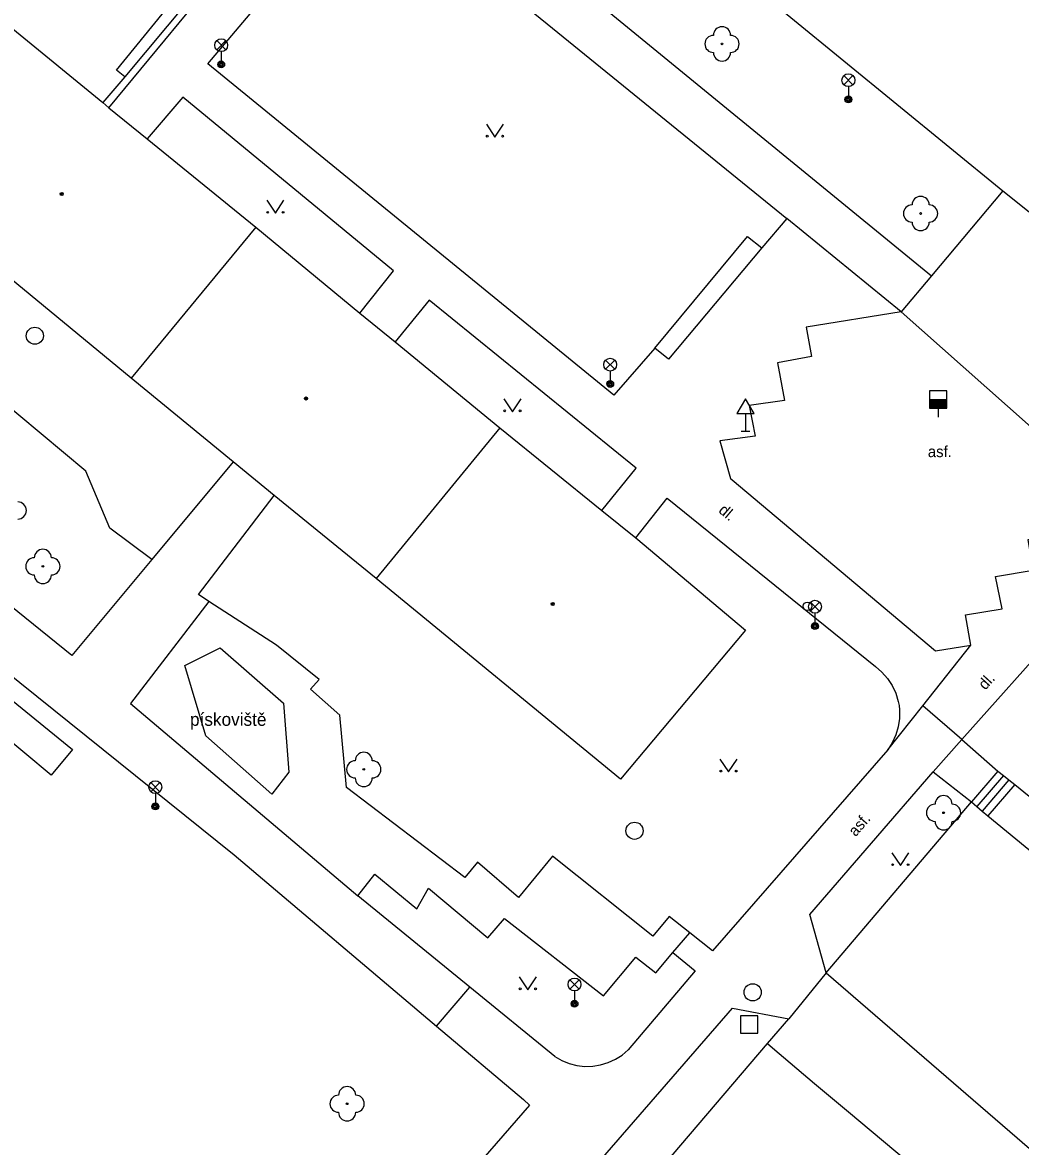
# Model space of a CAD drawing. Extents: x -598932 to -598196, y -1162207 to -1161504.
# Drawn here: x -598545.9 to -598487.7, y -1161944.1 to -1161878.5 of the extents above; entities that cross this region are included whole.
import ezdxf

# ---------------------------------------------------------------- set-up
doc = ezdxf.new("R2010")
doc.units = 0
for name, color, linetype in [('Level 22', 7, 'Continuous'), ('Level 26', 7, 'Continuous'), ('Level 27', 7, 'Continuous'), ('Level 28', 7, 'Continuous'), ('Level 33', 7, 'Continuous'), ('Level 34', 7, 'Continuous'), ('Level 36', 7, 'Continuous'), ('Level 39', 7, 'Continuous'), ('specificka linie pasportu komunikaci', 7, 'Continuous'), ('TM - budovy zdene_ betonove - VP', 7, 'Continuous'), ('TM - chodniky - VP', 7, 'Continuous'), ('TM - komunikace - VP', 7, 'Continuous'), ('TM - letecke snimky - pomocna linie', 7, 'Continuous'), ('TM - plot dreveny_ kovovy - VP', 7, 'Continuous'), ('TM - popis povrchu', 7, 'Continuous'), ('TM - poznamka', 7, 'Continuous'), ('TM - rozhrani ploch obecne - VP', 7, 'Continuous'), ('TM - schody - VP', 7, 'Continuous'), ('TM - vjezd na pozemek', 7, 'Continuous')]:
    doc.layers.add(name, color=color, linetype=linetype)

msp = doc.modelspace()

# ---------------------------------------------------------------- linework, layer by layer
at = {"layer": 'Level 22'}
for centre in [(-598505.14, -1161879.76), (-598493.56, -1161889.65), (-598544.74, -1161910.23), (-598526.03, -1161922.07), (-598492.22, -1161924.6), (-598527, -1161941.57)]:
    msp.add_circle(centre, 0.05, dxfattribs=at)
for centre, start, end in [((-598505.14, -1161879.26), 0, 180), ((-598505.64, -1161879.76), 90, 270), ((-598504.64, -1161879.76), 270, 90), ((-598505.14, -1161880.26), 180, 0), ((-598493.56, -1161889.15), 0, 180), ((-598494.06, -1161889.65), 90, 270), ((-598493.06, -1161889.65), 270, 90), ((-598493.56, -1161890.15), 180, 0), ((-598546.2, -1161906.97), 270, 90), ((-598544.74, -1161909.73), 0, 180), ((-598545.24, -1161910.23), 90, 270), ((-598544.24, -1161910.23), 270, 90), ((-598544.74, -1161910.73), 180, 0), ((-598526.03, -1161921.57), 0, 180), ((-598526.53, -1161922.07), 90, 270), ((-598525.53, -1161922.07), 270, 90), ((-598526.03, -1161922.57), 180, 0), ((-598492.22, -1161924.1), 0, 180), ((-598492.72, -1161924.6), 90, 270), ((-598491.72, -1161924.6), 270, 90), ((-598492.22, -1161925.1), 180, 0), ((-598527, -1161941.07), 0, 180), ((-598527.5, -1161941.57), 90, 270), ((-598526.5, -1161941.57), 270, 90), ((-598527, -1161942.07), 180, 0)]:
    msp.add_arc(centre, 0.5, start, end, dxfattribs=at)
at = {"layer": 'Level 26'}
msp.add_lwpolyline([(-598504.06, -1161937.45), (-598503.06, -1161937.45), (-598503.06, -1161936.45), (-598504.06, -1161936.45)], close=True, dxfattribs=at)
at = {"layer": 'Level 27'}
for centre in [(-598545.21, -1161896.78), (-598510.24, -1161925.65), (-598503.35, -1161935.07)]:
    msp.add_circle(centre, 0.5, dxfattribs=at)
at = {"layer": 'Level 28'}
for p, q in [((-598493.04, -1161900.5), (-598492.04, -1161900.5)), ((-598493.04, -1161900.55), (-598492.04, -1161900.55)), ((-598493.04, -1161900.6), (-598492.04, -1161900.6)), ((-598493.04, -1161900.65), (-598492.04, -1161900.65)), ((-598493.04, -1161900.7), (-598492.04, -1161900.7)), ((-598493.04, -1161900.75), (-598492.04, -1161900.75)), ((-598493.04, -1161900.8), (-598492.04, -1161900.8)), ((-598493.04, -1161900.85), (-598492.04, -1161900.85)), ((-598493.04, -1161900.9), (-598492.04, -1161900.9)), ((-598493.04, -1161900.95), (-598492.04, -1161900.95)), ((-598492.54, -1161901), (-598492.54, -1161901.53))]:
    msp.add_line(p, q, dxfattribs=at)
msp.add_lwpolyline([(-598493.04, -1161901), (-598492.04, -1161901), (-598492.04, -1161900), (-598493.04, -1161900)], close=True, dxfattribs=at)
msp.add_circle((-598500.16, -1161912.56), 0.25, dxfattribs=at)
at = {"layer": 'Level 33'}
for p, q in [((-598534.605, -1161880.1), (-598534.075, -1161879.57)), ((-598534.605, -1161879.57), (-598534.075, -1161880.1)), ((-598534.34, -1161880.21), (-598534.34, -1161880.96)), ((-598498.035, -1161882.14), (-598497.505, -1161881.61)), ((-598498.035, -1161881.61), (-598497.505, -1161882.14)), ((-598497.77, -1161882.25), (-598497.77, -1161883)), ((-598511.925, -1161898.73), (-598511.395, -1161898.2)), ((-598511.925, -1161898.2), (-598511.395, -1161898.73)), ((-598511.66, -1161898.84), (-598511.66, -1161899.59)), ((-598499.985, -1161912.85), (-598499.455, -1161912.32)), ((-598499.985, -1161912.32), (-598499.455, -1161912.85)), ((-598499.72, -1161912.96), (-598499.72, -1161913.71)), ((-598538.445, -1161923.37), (-598537.915, -1161922.84)), ((-598538.445, -1161922.84), (-598537.915, -1161923.37)), ((-598538.18, -1161923.48), (-598538.18, -1161924.23)), ((-598514.005, -1161934.88), (-598513.475, -1161934.35)), ((-598514.005, -1161934.35), (-598513.475, -1161934.88)), ((-598513.74, -1161934.99), (-598513.74, -1161935.74))]:
    msp.add_line(p, q, dxfattribs=at)
for centre, radius in [((-598534.34, -1161879.835), 0.375), ((-598534.34, -1161880.96), 0.2), ((-598534.34, -1161880.96), 0.145), ((-598534.34, -1161880.96), 0.0876), ((-598497.77, -1161881.875), 0.375), ((-598497.77, -1161883), 0.2), ((-598497.77, -1161883), 0.145), ((-598497.77, -1161883), 0.0876), ((-598511.66, -1161898.465), 0.375), ((-598511.66, -1161899.59), 0.2), ((-598511.66, -1161899.59), 0.145), ((-598511.66, -1161899.59), 0.0876), ((-598499.72, -1161912.585), 0.375), ((-598499.72, -1161913.71), 0.2), ((-598499.72, -1161913.71), 0.145), ((-598499.72, -1161913.71), 0.0876), ((-598538.18, -1161923.105), 0.375), ((-598538.18, -1161924.23), 0.2), ((-598538.18, -1161924.23), 0.145), ((-598538.18, -1161924.23), 0.0876), ((-598513.74, -1161934.615), 0.375), ((-598513.74, -1161935.74), 0.2), ((-598513.74, -1161935.74), 0.145), ((-598513.74, -1161935.74), 0.0876)]:
    msp.add_circle(centre, radius, dxfattribs=at)
at = {"layer": 'Level 34'}
for p, q in [((-598503.77, -1161901.322), (-598503.77, -1161902.34)), ((-598504.02, -1161902.34), (-598503.52, -1161902.34))]:
    msp.add_line(p, q, dxfattribs=at)
msp.add_lwpolyline([(-598504.27, -1161901.322), (-598503.27, -1161901.322), (-598503.77, -1161900.456)], close=True, dxfattribs=at)
at = {"layer": 'Level 36'}
for points in [[(-598518.88, -1161884.44), (-598518.38, -1161885.19), (-598517.88, -1161884.44)], [(-598531.68, -1161888.88), (-598531.18, -1161889.63), (-598530.68, -1161888.88)], [(-598517.86, -1161900.46), (-598517.36, -1161901.21), (-598516.86, -1161900.46)], [(-598505.26, -1161921.47), (-598504.76, -1161922.22), (-598504.26, -1161921.47)], [(-598495.24, -1161926.93), (-598494.74, -1161927.68), (-598494.24, -1161926.93)], [(-598516.96, -1161934.17), (-598516.46, -1161934.92), (-598515.96, -1161934.17)]]:
    msp.add_lwpolyline(points, dxfattribs=at)
for centre in [(-598518.83, -1161885.14), (-598517.931, -1161885.14), (-598531.63, -1161889.58), (-598530.731, -1161889.58), (-598517.81, -1161901.16), (-598516.911, -1161901.16), (-598505.21, -1161922.17), (-598504.311, -1161922.17), (-598495.19, -1161927.63), (-598494.291, -1161927.63), (-598516.91, -1161934.87), (-598516.011, -1161934.87)]:
    msp.add_circle(centre, 0.05, dxfattribs=at)
at = {"layer": 'Level 39'}
for centre, radius in [((-598543.64, -1161888.51), 0.09), ((-598543.64, -1161888.51), 0.0398), ((-598529.4, -1161900.44), 0.09), ((-598529.4, -1161900.44), 0.0398), ((-598515.01, -1161912.42), 0.09), ((-598515.01, -1161912.42), 0.0398)]:
    msp.add_circle(centre, radius, dxfattribs=at)
at = {"layer": 'specificka linie pasportu komunikaci'}
for points in [[(-598486.09, -1161903.02), (-598494.7, -1161895.38)], [(-598508.01, -1161932.75), (-598507.01, -1161931.61)], [(-598521.79, -1161937.04), (-598519.84, -1161934.78)]]:
    msp.add_lwpolyline(points, dxfattribs=at)
at = {"layer": 'TM - budovy zdene_ betonove - VP'}
for points in [[(-598546.49, -1161878.88), (-598541.24, -1161883.18)], [(-598541.24, -1161883.18), (-598540.89, -1161883.48)], [(-598540.89, -1161883.48), (-598538.66, -1161885.3)], [(-598538.66, -1161885.3), (-598532.32, -1161890.45)], [(-598539.6, -1161899.25), (-598553.72, -1161887.6)], [(-598532.32, -1161890.45), (-598539.6, -1161899.25)], [(-598532.32, -1161890.45), (-598526.25, -1161895.47)], [(-598526.25, -1161895.47), (-598524.19, -1161897.14)], [(-598524.19, -1161897.14), (-598518.09, -1161902.15)], [(-598533.65, -1161904.14), (-598539.6, -1161899.25)], [(-598518.09, -1161902.15), (-598525.3, -1161910.94)], [(-598518.09, -1161902.15), (-598512.15, -1161906.98)], [(-598531.25, -1161906.1), (-598533.65, -1161904.14)], [(-598525.3, -1161910.94), (-598531.25, -1161906.1)], [(-598512.15, -1161906.98), (-598510.17, -1161908.57)], [(-598510.17, -1161908.57), (-598503.77, -1161913.96)], [(-598511.05, -1161922.65), (-598525.3, -1161910.94)], [(-598503.77, -1161913.96), (-598511.05, -1161922.65)], [(-598526.29, -1161965.99), (-598502.49, -1161938.05)], [(-598502.49, -1161938.05), (-598502.19, -1161938.3)], [(-598502.19, -1161938.3), (-598499.74, -1161940.39)], [(-598499.74, -1161940.39), (-598497.76, -1161942.05)], [(-598497.76, -1161942.05), (-598494.41, -1161944.87)]]:
    msp.add_lwpolyline(points, dxfattribs=at)
at = {"layer": 'TM - chodniky - VP'}
for points in [[(-598530.4, -1161862.6), (-598492.92, -1161893.29)], [(-598603.15, -1161870.38), (-598584.47, -1161885.72), (-598557.6, -1161907.74), (-598533.59, -1161927.06)], [(-598511.45, -1161900.24), (-598535.13, -1161880.92), (-598525.89, -1161870), (-598501.37, -1161889.95)], [(-598540.89, -1161883.48), (-598533.52, -1161874.57)], [(-598526.25, -1161895.47), (-598524.3, -1161892.99), (-598536.57, -1161882.87), (-598538.66, -1161885.3)], [(-598538.39, -1161909.83), (-598540.84, -1161908), (-598542.23, -1161904.67), (-598550.07, -1161898.15), (-598555.22, -1161899.67), (-598559.74, -1161895.99), (-598557.48, -1161892.2), (-598559.61, -1161890.72), (-598558.55, -1161889.53), (-598560.88, -1161887.56), (-598561.78, -1161888.66), (-598563.39, -1161887.27)], [(-598501.37, -1161889.95), (-598502.81, -1161891.66)], [(-598502.81, -1161891.66), (-598508.26, -1161898.15), (-598509.06, -1161897.51)], [(-598512.15, -1161906.98), (-598510.14, -1161904.5), (-598522.22, -1161894.71), (-598524.19, -1161897.14)], [(-598509.06, -1161897.51), (-598511.45, -1161900.24)], [(-598533.65, -1161904.14), (-598538.39, -1161909.83)], [(-598535.07, -1161912.27), (-598535.67, -1161911.88), (-598531.25, -1161906.1)], [(-598510.17, -1161908.57), (-598508.33, -1161906.25), (-598496.19, -1161916.07)], [(-598479.84, -1161907.65), (-598491.16, -1161920.33)], [(-598515.02, -1161927.14), (-598517.01, -1161929.55), (-598519.4, -1161927.49), (-598520.13, -1161928.38), (-598527.04, -1161923.13), (-598527.42, -1161918.9), (-598529.14, -1161917.4), (-598528.63, -1161916.83), (-598531.12, -1161914.82), (-598535.07, -1161912.27)], [(-598496.19, -1161916.07), (-598495.812, -1161916.392), (-598495.485, -1161916.765), (-598495.214, -1161917.181), (-598495.006, -1161917.632), (-598494.865, -1161918.107), (-598494.82, -1161918.35), (-598494.793, -1161918.598), (-598494.792, -1161919.095), (-598494.863, -1161919.586), (-598495.003, -1161920.062), (-598495.21, -1161920.513), (-598495.48, -1161920.93)], [(-598491.16, -1161920.33), (-598489.05, -1161922.17)], [(-598495.48, -1161920.93), (-598505.7, -1161932.65)], [(-598499.07, -1161933.94), (-598500.02, -1161930.53), (-598492.83, -1161922.22)], [(-598492.83, -1161922.22), (-598490.59, -1161923.96)], [(-598489.05, -1161922.17), (-598488.73, -1161922.43)], [(-598488.73, -1161922.43), (-598488.41, -1161922.68)], [(-598488.41, -1161922.68), (-598488.07, -1161922.95)], [(-598488.07, -1161922.95), (-598480.35, -1161929.24), (-598478.28, -1161926.8)], [(-598533.59, -1161927.06), (-598521.79, -1161937.04), (-598516.72, -1161941.32), (-598516.36, -1161941.65), (-598532.71, -1161960.46)], [(-598505.7, -1161932.65), (-598507.01, -1161931.61), (-598508.23, -1161930.65), (-598509.18, -1161931.79), (-598515.02, -1161927.14)], [(-598526.37, -1161929.45), (-598525.38, -1161928.18), (-598522.94, -1161930.2), (-598522.26, -1161929), (-598518.79, -1161931.89), (-598517.83, -1161930.77)], [(-598514.89, -1161938.82), (-598519.84, -1161934.78), (-598526.37, -1161929.45)], [(-598517.83, -1161930.77), (-598512.05, -1161935.28), (-598510.16, -1161933.03), (-598508.99, -1161933.94), (-598508.01, -1161932.75), (-598506.71, -1161933.81)], [(-598506.71, -1161933.81), (-598510.61, -1161938.43)], [(-598499.07, -1161933.94), (-598486.35, -1161944.91)], [(-598530.97, -1161962), (-598528.77, -1161963.92), (-598504.53, -1161935.99), (-598501.24, -1161936.61)], [(-598514.89, -1161938.82), (-598514.487, -1161939.051), (-598514.057, -1161939.225), (-598513.607, -1161939.339), (-598513.145, -1161939.391), (-598512.68, -1161939.38), (-598512.223, -1161939.307), (-598511.778, -1161939.172), (-598511.356, -1161938.979), (-598510.965, -1161938.73), (-598510.61, -1161938.43)]]:
    msp.add_lwpolyline(points, dxfattribs=at)
at = {"layer": 'TM - komunikace - VP'}
for points in [[(-598526.36, -1161857.65), (-598516.58, -1161865.57), (-598488.77, -1161888.33)], [(-598488.77, -1161888.33), (-598492.92, -1161893.29)], [(-598492.92, -1161893.29), (-598494.7, -1161895.38)], [(-598494.7, -1161895.38), (-598500.24, -1161896.27)], [(-598500.24, -1161896.27), (-598499.93, -1161898), (-598501.9, -1161898.35), (-598501.5, -1161900.55), (-598503.56, -1161900.85), (-598503.21, -1161902.63), (-598505.27, -1161902.91), (-598504.64, -1161905.11), (-598504.557, -1161905.179)], [(-598490.63, -1161914.83), (-598490.94, -1161913.06), (-598488.81, -1161912.71), (-598489.2, -1161910.83), (-598486.99, -1161910.45), (-598487.29, -1161908.67), (-598485.34, -1161908.4), (-598486.09, -1161903.02)], [(-598504.557, -1161905.179), (-598492.7, -1161915.15)], [(-598492.7, -1161915.15), (-598490.63, -1161914.83)]]:
    msp.add_lwpolyline(points, dxfattribs=at)
at = {"layer": 'TM - letecke snimky - pomocna linie'}
for points in [[(-598538.39, -1161909.83), (-598543.05, -1161915.43), (-598568.95, -1161894.5), (-598567.31, -1161892.15)], [(-598535.07, -1161912.27), (-598539.63, -1161918.23), (-598526.37, -1161929.45)]]:
    msp.add_lwpolyline(points, dxfattribs=at)
at = {"layer": 'TM - plot dreveny_ kovovy - VP'}
for points in [[(-598499.07, -1161933.94), (-598490.59, -1161923.96)], [(-598490.59, -1161923.96), (-598490.28, -1161924.23)], [(-598490.28, -1161924.23), (-598489.97, -1161924.5)], [(-598489.97, -1161924.5), (-598489.65, -1161924.78)], [(-598489.65, -1161924.78), (-598452.66, -1161955.16)], [(-598502.49, -1161938.05), (-598501.24, -1161936.61)]]:
    msp.add_lwpolyline(points, dxfattribs=at)
at = {"layer": 'TM - rozhrani ploch obecne - VP'}
for points in [[(-598539.97, -1161881.68), (-598540.44, -1161881.3), (-598535.54, -1161875.27), (-598533.84, -1161874.33)], [(-598533.84, -1161874.33), (-598539.97, -1161881.68)], [(-598539.97, -1161881.68), (-598541.24, -1161883.18)], [(-598488.77, -1161888.33), (-598484.53, -1161891.71), (-598480.01, -1161895.48)], [(-598494.7, -1161895.38), (-598501.37, -1161889.95)], [(-598509.06, -1161897.51), (-598503.66, -1161890.99), (-598502.81, -1161891.66)], [(-598531.39, -1161923.51), (-598535.23, -1161920.11), (-598536.46, -1161916.01), (-598534.41, -1161914.99), (-598530.71, -1161918.21), (-598530.39, -1161922.24), (-598531.39, -1161923.51)], [(-598493.44, -1161918.36), (-598490.63, -1161914.83)], [(-598547.64, -1161917.15), (-598543.02, -1161920.92), (-598544.25, -1161922.41), (-598548.89, -1161918.56)], [(-598495.48, -1161920.93), (-598493.44, -1161918.36)], [(-598491.16, -1161920.33), (-598493.44, -1161918.36)], [(-598492.83, -1161922.22), (-598491.16, -1161920.33)], [(-598489.05, -1161922.17), (-598490.59, -1161923.96)], [(-598488.07, -1161922.95), (-598489.65, -1161924.78)]]:
    msp.add_lwpolyline(points, dxfattribs=at)
at = {"layer": 'TM - schody - VP'}
for points in [[(-598488.73, -1161922.43), (-598490.28, -1161924.23)], [(-598488.41, -1161922.68), (-598489.97, -1161924.5)]]:
    msp.add_lwpolyline(points, dxfattribs=at)
at = {"layer": 'TM - vjezd na pozemek'}
msp.add_lwpolyline([(-598499.07, -1161933.94), (-598501.24, -1161936.61)], dxfattribs=at)

# ---------------------------------------------------------------- texts
at = {"layer": 'TM - popis povrchu'}
msp.add_text('asf.', height=0.65, dxfattribs=at).set_placement((-598493.14, -1161903.86))
for s, rotation, p in [('dl.', 319.99, (-598505.39, -1161907.04)), ('dl.', 47.78, (-598489.79, -1161917.48)), ('asf.', 49.13, (-598497.35, -1161926.03))]:
    msp.add_text(s, height=0.65, rotation=rotation, dxfattribs=at).set_placement(p)
at = {"layer": 'TM - poznamka'}
msp.add_text('pískoviště', height=0.75, dxfattribs=at).set_placement((-598536.16, -1161919.53))

doc.saveas('drawing.dxf')
